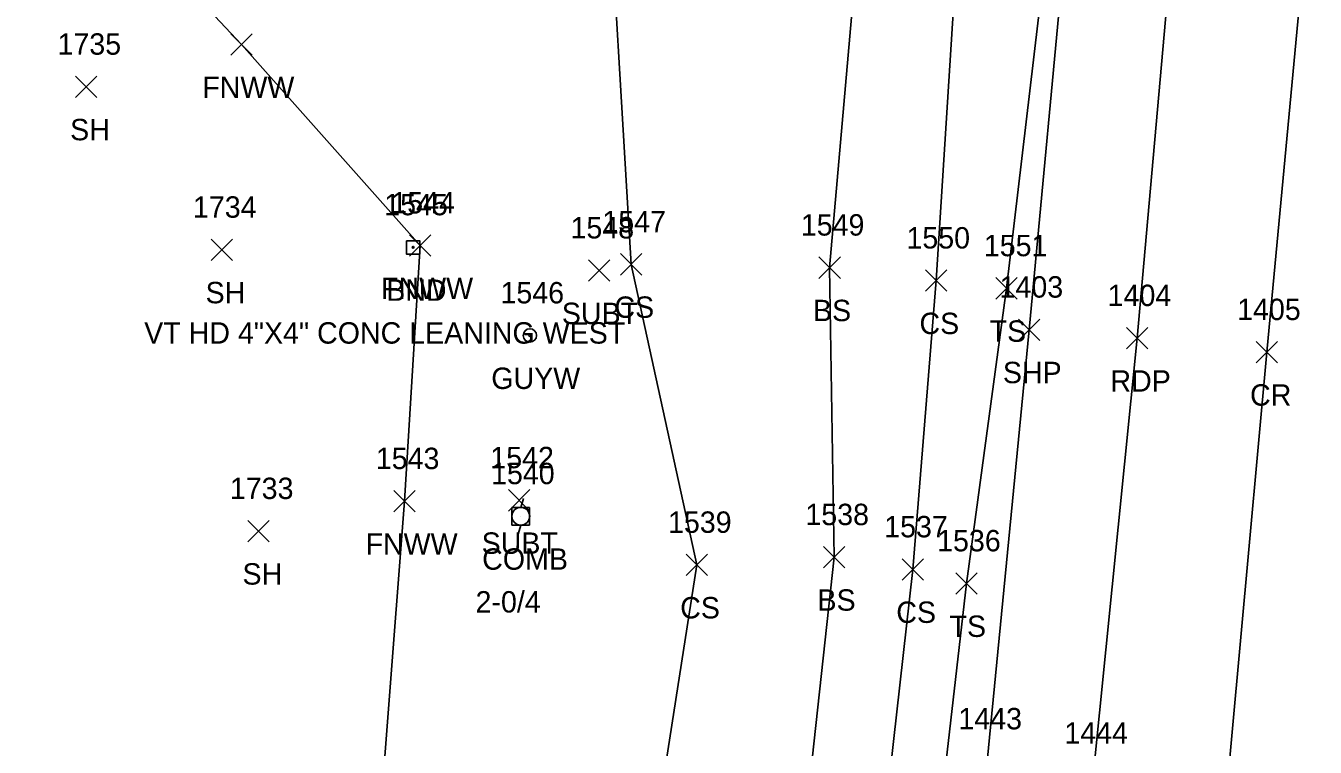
# Model space of a CAD drawing. Extents: x 1443960 to 1446865, y 610387 to 616706.
# Drawn here: x 1446473.8 to 1446594.4, y 611010.8 to 611078.2 of the extents above; entities that cross this region are included whole.
import ezdxf

# ---------------------------------------------------------------- set-up
doc = ezdxf.new("R2010")
doc.units = 0
for name, color, linetype in [('L_A', 7, 'Continuous'), ('L_I', 7, 'Continuous'), ('L_TIC', 7, 'Continuous'), ('LELB', 7, 'Continuous'), ('LFNC', 7, 'Continuous'), ('M_A', 7, 'Continuous'), ('M_C', 7, 'Continuous'), ('M_I', 7, 'Continuous'), ('MHBP', 7, 'Continuous'), ('P_A', 7, 'Continuous'), ('P_I', 7, 'Continuous'), ('P_TIC', 7, 'Continuous'), ('PET', 7, 'Continuous'), ('PRC', 7, 'Continuous'), ('PSP', 7, 'Continuous'), ('U_A', 7, 'Continuous'), ('U_C', 7, 'Continuous'), ('U_I', 7, 'Continuous'), ('U_TIC', 7, 'Continuous'), ('UP', 7, 'Continuous'), ('UPGW', 7, 'Continuous')]:
    doc.layers.add(name, color=color, linetype=linetype)

msp = doc.modelspace()

# ---------------------------------------------------------------- linework, layer by layer
at = {"layer": 'L_TIC'}
for points in [[(1446493.01, 611075.45), (1446495.01, 611077.45)], [(1446495.01, 611075.45), (1446493.01, 611077.45)], [(1446478.5, 611071.5), (1446480.5, 611073.5)], [(1446480.5, 611071.5), (1446478.5, 611073.5)], [(1446491.17, 611056.26), (1446493.17, 611058.26)], [(1446493.17, 611056.26), (1446491.17, 611058.26)], [(1446509.72, 611056.66), (1446511.72, 611058.66)], [(1446511.72, 611056.66), (1446509.72, 611058.66)], [(1446529.46, 611054.9), (1446531.46, 611056.9)], [(1446531.46, 611054.9), (1446529.46, 611056.9)], [(1446548.03, 611054.59), (1446550.03, 611056.59)], [(1446550.03, 611054.59), (1446548.03, 611056.59)], [(1446557.99, 611053.38), (1446559.99, 611055.38)], [(1446559.99, 611053.38), (1446557.99, 611055.38)], [(1446564.58, 611052.66), (1446566.58, 611054.66)], [(1446566.58, 611052.66), (1446564.58, 611054.66)], [(1446508.27, 611032.76), (1446510.27, 611034.76)], [(1446510.27, 611032.76), (1446508.27, 611034.76)], [(1446494.62, 611029.96), (1446496.62, 611031.96)], [(1446496.62, 611029.96), (1446494.62, 611031.96)], [(1446548.45, 611027.52), (1446550.45, 611029.52)], [(1446550.45, 611027.52), (1446548.45, 611029.52)], [(1446535.61, 611026.8), (1446537.61, 611028.8)], [(1446537.61, 611026.8), (1446535.61, 611028.8)], [(1446555.82, 611026.38), (1446557.82, 611028.38)], [(1446557.82, 611026.38), (1446555.82, 611028.38)], [(1446560.83, 611025.07), (1446562.83, 611027.07)], [(1446562.83, 611025.07), (1446560.83, 611027.07)]]:
    msp.add_lwpolyline(points, dxfattribs=at)
at = {"layer": 'LELB'}
for points in [[(1446548.85, 610888.19), (1446553.44, 610932.22), (1446554.61, 610954.43), (1446557.18, 610985.54), (1446561.83, 611026.07), (1446565.58, 611053.66), (1446570.69, 611096.92), (1446573.29, 611130.79), (1446568.51, 611145), (1446569.91, 611148.66), (1446564.88, 611156.7), (1446536.84, 611169.59), (1446508.69, 611183.48), (1446466.55, 611207.56), (1446427.27, 611227.8), (1446388.8, 611245), (1446349.69, 611268.25), (1446343.09, 611268.96)], [(1446545.33, 610990.77), (1446549.45, 611028.52), (1446549.03, 611055.59), (1446553.29, 611104.25), (1446542.01, 611115.66), (1446540.05, 611127.24), (1446544.04, 611129.96), (1446551.51, 611136.49), (1446553.27, 611138.91), (1446550.53, 611149.51), (1446533.12, 611159.93), (1446498.33, 611176.52), (1446468.4, 611193.46), (1446432.91, 611211.11), (1446396.49, 611230.29), (1446366.67, 611244.64), (1446348.43, 611256.48)], [(1446530.86, 610991.05), (1446536.61, 611027.8), (1446530.46, 611055.9), (1446528.01, 611097.29), (1446529.9, 611126.45), (1446531.13, 611139.44), (1446489.18, 611159.91), (1446465.02, 611182.42), (1446422.58, 611193.97), (1446390.63, 611222.09), (1446361.12, 611230.87), (1446345.74, 611242.49)], [(1446552.56, 610989.66), (1446556.82, 611027.38), (1446558.99, 611054.38), (1446562.05, 611102.47), (1446562.29, 611110), (1446552.62, 611117.46), (1446544.98, 611124.73), (1446545.64, 611126.22), (1446556.66, 611130.04), (1446565.54, 611129.7), (1446560.88, 611143.04), (1446563.36, 611147.94)]]:
    msp.add_lwpolyline(points, dxfattribs=at)
at = {"layer": 'LFNC'}
for points in [[(1446494.01, 611076.45), (1446487.06, 611083.87)], [(1446496.64, 610892.92), (1446500.33, 610934.58), (1446502.47, 610957.54), (1446506.14, 610993.3), (1446509.27, 611033.76), (1446510.72, 611057.66), (1446494.01, 611076.45)]]:
    msp.add_lwpolyline(points, dxfattribs=at)
at = {"layer": 'MHBP'}
msp.add_lwpolyline([(1446509.44, 611058.11), (1446510.69, 611058.11), (1446510.69, 611056.86), (1446509.44, 611056.86)], close=True, dxfattribs=at)
msp.add_circle((1446510.07, 611057.49), 0.0833, dxfattribs=at)
at = {"layer": 'P_TIC'}
for points in [[(1446566.69, 611048.79), (1446568.69, 611050.79)], [(1446568.69, 611048.79), (1446566.69, 611050.79)], [(1446576.8, 611048), (1446578.8, 611050)], [(1446578.8, 611048), (1446576.8, 611050)], [(1446588.92, 611046.69), (1446590.92, 611048.69)], [(1446590.92, 611046.69), (1446588.92, 611048.69)]]:
    msp.add_lwpolyline(points, dxfattribs=at)
at = {"layer": 'PET'}
msp.add_lwpolyline([(1446586.96, 611148.93), (1446585.91, 611138.65), (1446581.07, 611085.82), (1446577.8, 611049), (1446573.67, 611008.09), (1446567.43, 610950.16), (1446562.94, 610911.75), (1446557.73, 610863.22), (1446550.26, 610797.89), (1446543.48, 610732.42), (1446535.83, 610665.01), (1446522.7, 610589.27)], dxfattribs=at)
at = {"layer": 'PRC'}
msp.add_lwpolyline([(1446598.39, 611142.94), (1446597.49, 611132.62), (1446593.4, 611084.97), (1446589.92, 611047.69), (1446585, 610993.71), (1446580.73, 610956.9), (1446575.28, 610909.2), (1446570.19, 610861.52)], dxfattribs=at)
at = {"layer": 'PSP'}
msp.add_lwpolyline([(1446576.92, 611154.08), (1446576.88, 611153.48), (1446576.38, 611146.03), (1446571.14, 611086.78), (1446567.69, 611049.79), (1446563.76, 611009.43), (1446561.38, 610989.08), (1446557.86, 610953.83), (1446553.98, 610913.79), (1446549.11, 610862.52), (1446542.65, 610799.79), (1446535.25, 610731.33), (1446527.9, 610668.85), (1446515.47, 610590.43)], dxfattribs=at)
at = {"layer": 'U_TIC'}
for points in [[(1446526.48, 611054.32), (1446528.48, 611056.32)], [(1446528.48, 611054.32), (1446526.48, 611056.32)], [(1446518.99, 611032.84), (1446520.99, 611034.84)], [(1446520.99, 611032.84), (1446518.99, 611034.84)]]:
    msp.add_lwpolyline(points, dxfattribs=at)
at = {"layer": 'UP'}
for p, q in [((1446520.39, 611034.02), (1446520.14, 611033.18)), ((1446519.31, 611031.52), (1446519.31, 611033.18)), ((1446519.31, 611033.18), (1446520.97, 611033.18)), ((1446520.97, 611033.18), (1446520.97, 611031.52)), ((1446520.97, 611031.52), (1446519.31, 611031.52)), ((1446519.89, 611030.68), (1446520.14, 611031.52)), ((1446520.14, 611032.35), (1446520.14, 611032.35))]:
    msp.add_line(p, q, dxfattribs=at)
msp.add_circle((1446520.14, 611032.35), 0.833, dxfattribs=at)
at = {"layer": 'UPGW'}
for radius in [0.625, 0.0833]:
    msp.add_circle((1446520.99, 611049.25), radius, dxfattribs=at)

# ---------------------------------------------------------------- texts
at = {"layer": 'L_A'}
for s, p in [('FNWW', (1446490.35, 611071.45)), ('SH', (1446477.99, 611067.5)), ('SH', (1446490.66, 611052.26)), ('FNWW', (1446507.07, 611052.66)), ('CS', (1446528.9, 611050.9)), ('BS', (1446547.47, 611050.59)), ('CS', (1446557.43, 611049.38)), ('TS', (1446563.99, 611048.66)), ('FNWW', (1446505.62, 611028.76)), ('SH', (1446494.11, 611025.96)), ('BS', (1446547.89, 611023.52)), ('CS', (1446535.05, 611022.8)), ('CS', (1446555.26, 611022.38)), ('TS', (1446560.24, 611021.07))]:
    msp.add_text(s, height=2, dxfattribs=at).set_placement(p)
at = {"layer": 'L_I'}
for s, p in [('1735', (1446476.81, 611075.5)), ('1544', (1446508.03, 611060.66)), ('1734', (1446489.48, 611060.26)), ('1547', (1446527.77, 611058.9)), ('1549', (1446546.33, 611058.59)), ('1550', (1446556.21, 611057.38)), ('1551', (1446563.45, 611056.66)), ('1543', (1446506.58, 611036.76)), ('1733', (1446492.93, 611033.96)), ('1539', (1446533.91, 611030.8)), ('1538', (1446546.76, 611031.52)), ('1537', (1446554.13, 611030.38)), ('1536', (1446559.08, 611029.07))]:
    msp.add_text(s, height=2, dxfattribs=at).set_placement(p)
at = {"layer": 'M_A'}
msp.add_text('BND', height=2, dxfattribs=at).set_placement((1446507.55, 611052.49))
at = {"layer": 'M_C'}
msp.add_text('VT HD 4"X4" CONC LEANING WEST', height=2, dxfattribs=at).set_placement((1446484.92, 611048.49))
at = {"layer": 'M_I'}
msp.add_text('1545', height=2, dxfattribs=at).set_placement((1446507.37, 611060.49))
at = {"layer": 'P_A'}
for s, p in [('SHP', (1446565.23, 611044.79)), ('RDP', (1446575.29, 611044)), ('CR', (1446588.35, 611042.69))]:
    msp.add_text(s, height=2, dxfattribs=at).set_placement(p)
at = {"layer": 'P_I'}
for s, p in [('1403', (1446564.92, 611052.79)), ('1404', (1446575.03, 611052)), ('1405', (1446587.14, 611050.69)), ('1443', (1446561.07, 611012.43)), ('1444', (1446570.98, 611011.09))]:
    msp.add_text(s, height=2, dxfattribs=at).set_placement(p)
at = {"layer": 'U_A'}
for s, p in [('SUBT', (1446523.98, 611050.32)), ('GUYW', (1446517.38, 611044.25)), ('SUBT', (1446516.48, 611028.84)), ('COMB', (1446516.53, 611027.35))]:
    msp.add_text(s, height=2, dxfattribs=at).set_placement(p)
at = {"layer": 'U_C'}
msp.add_text('2-0/4', height=2, dxfattribs=at).set_placement((1446515.91, 611023.35))
at = {"layer": 'U_I'}
for s, p in [('1548', (1446524.79, 611058.32)), ('1546', (1446518.24, 611052.25)), ('1542', (1446517.29, 611036.84)), ('1540', (1446517.36, 611035.35))]:
    msp.add_text(s, height=2, dxfattribs=at).set_placement(p)

doc.saveas('drawing.dxf')
